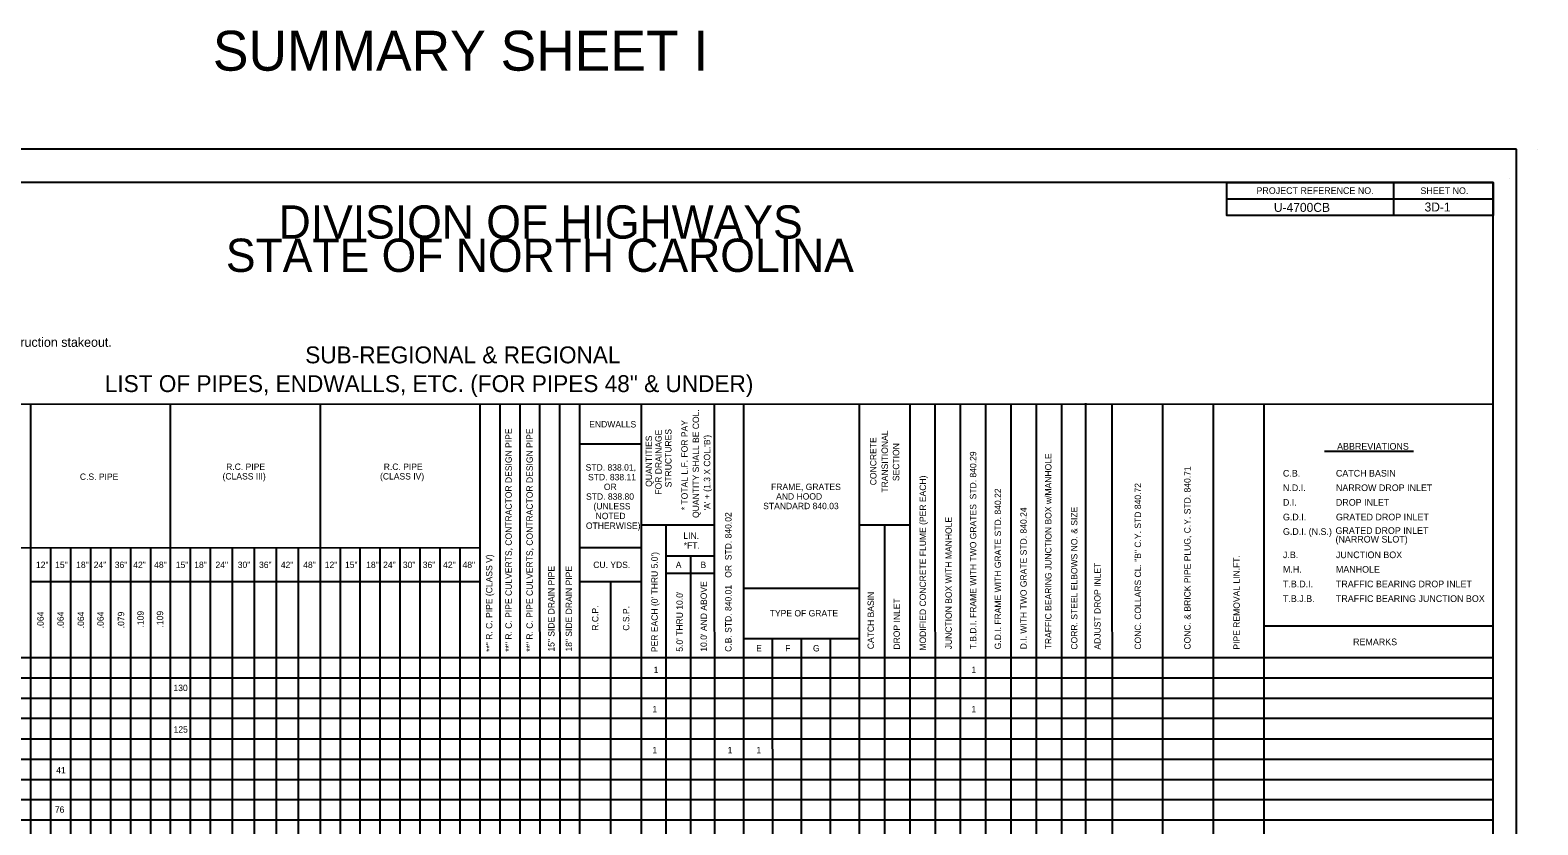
# Model space of a CAD drawing. Extents: x 809447 to 814738, y 647528 to 651206.
# Drawn here: x 810014 to 811147, y 650609 to 651206 of the extents above; entities that cross this region are included whole.
import ezdxf

# ---------------------------------------------------------------- set-up
doc = ezdxf.new("R2010")
doc.units = 0
doc.layers.add('Default', color=7, linetype='Continuous')
doc.layers.add('Old_Level_44', color=7, linetype='Continuous')

msp = doc.modelspace()

# ---------------------------------------------------------------- linework, layer by layer
at = {"layer": 'Default'}
for p, q in [((811147.1, 651116.9), (811147.1, 651116.9)), ((811147.1, 651116.9), (811147.1, 651116.9)), ((811147.1, 651116.9), (811147.1, 651116.9)), ((811038.6, 651091.9), (811038.6, 651066.9)), ((811126.1, 651094.5), (811126.1, 651094.5)), ((811126.1, 651094.5), (811126.1, 651094.5)), ((811126.1, 651094.5), (811126.1, 651094.5)), ((810913.5, 651079.4), (811113.6, 651079.4)), ((811113.6, 650925.1), (809613.6, 650925)), ((810014.9, 650154.3), (810014.9, 650925)), ((810119.9, 650154.3), (810119.9, 650925)), ((810232.5, 650154.3), (810232.4, 650925.1)), ((810352.5, 650154.3), (810352.4, 650925.1)), ((810367.5, 650154.3), (810367.4, 650925.1)), ((810382.5, 650154.3), (810382.4, 650925.1)), ((810397.5, 650154.3), (810397.4, 650925.1)), ((810412.5, 650154.3), (810412.4, 650925.1)), ((810427.5, 650154.3), (810427.4, 650925.1)), ((810427.4, 650154.3), (810427.4, 650925.1)), ((810427.5, 650154.3), (810427.4, 650925.1)), ((810473.7, 650154.3), (810473.6, 650925)), ((810528.7, 650154.3), (810528.6, 650925)), ((810528.7, 650154.3), (810528.6, 650925)), ((810550.5, 650154.3), (810550.5, 650925)), ((810637.5, 650154.3), (810637.4, 650925)), ((810675.5, 650154.3), (810675.4, 650925)), ((810694.5, 650154.3), (810694.4, 650925)), ((810713.5, 650154.3), (810713.4, 650925)), ((810732.5, 650154.3), (810732.4, 650925)), ((810751.5, 650154.3), (810751.4, 650925)), ((810770.5, 650154.3), (810770.4, 650925)), ((810789.5, 650154.3), (810789.4, 650925)), ((810807.6, 650155.2), (810807.5, 650925.9)), ((810827.5, 650154.3), (810827.4, 650925)), ((810827.5, 650154.3), (810827.4, 650925)), ((810865.5, 650154.3), (810865.4, 650925)), ((810865.5, 650154.3), (810865.4, 650925)), ((810903.5, 650154.3), (810903.4, 650925)), ((810903.5, 650154.3), (810903.4, 650925)), ((810941.5, 650154.3), (810941.4, 650925)), ((810941.5, 650154.3), (810941.4, 650925)), ((810473.6, 650895.1), (810427.4, 650895.1)), ((811053.7, 650889.6), (810986.7, 650889.6)), ((810527.4, 650834.3), (810473.6, 650834.3)), ((810492.3, 650154.3), (810492.2, 650834.3)), ((810675.4, 650834.3), (810637.4, 650834.3)), ((810656.5, 650154.3), (810656.4, 650834.3)), ((810352.4, 650817.2), (809834.9, 650817.1)), ((810029.9, 650154.3), (810029.9, 650817.1)), ((810044.9, 650154.3), (810044.9, 650817.2)), ((810059.9, 650154.3), (810059.9, 650817.1)), ((810074.9, 650154.3), (810074.9, 650817.2)), ((810089.9, 650154.3), (810089.9, 650817.1)), ((810104.9, 650154.3), (810104.9, 650817.2)), ((810119.9, 650154.3), (810119.9, 650817.1)), ((810134.9, 650154.3), (810134.9, 650817.2)), ((810149.9, 650154.3), (810149.9, 650817.2)), ((810166.4, 650154.3), (810166.4, 650817.2)), ((810182.9, 650154.3), (810182.9, 650817.2)), ((810199.4, 650154.3), (810199.4, 650817.2)), ((810215.9, 650154.3), (810215.9, 650817.2)), ((810232.4, 650154.3), (810232.4, 650817.2)), ((810247.4, 650154.3), (810247.4, 650817.2)), ((810262.4, 650154.3), (810262.4, 650817.2)), ((810277.4, 650154.3), (810277.4, 650817.2)), ((810292.4, 650154.3), (810292.4, 650817.2)), ((810307.4, 650154.3), (810307.4, 650817.2)), ((810322.4, 650154.3), (810322.4, 650817.2)), ((810337.4, 650154.3), (810337.4, 650817.2)), ((810352.4, 650154.3), (810352.4, 650817.2)), ((810473.6, 650817.2), (810427.4, 650817.2)), ((810528.6, 650811.1), (810492.2, 650811.1)), ((810510.9, 650154.3), (810510.8, 650811.1)), ((810528.6, 650797.9), (810492.2, 650797.9)), ((810352.4, 650791.8), (810014.9, 650791.8)), ((810014.9, 650154.3), (810014.9, 650791.8)), ((810473.6, 650791.8), (810427.4, 650791.8)), ((810450.6, 650154.3), (810450.5, 650791.8)), ((810637.4, 650786.8), (810550.5, 650786.8)), ((811113.6, 650758.5), (810941.4, 650758.5)), ((810637.4, 650749), (810550.5, 650749)), ((810572.3, 650154.3), (810572.2, 650749)), ((810594, 650154.3), (810593.9, 650749)), ((810615.7, 650154.3), (810615.7, 650749)), ((811113.6, 650734.7), (809613.6, 650734.7)), ((811113.6, 650719.4), (809613.6, 650719.4)), ((811113.6, 650704.1), (809613.6, 650704.1)), ((811113.6, 650688.9), (809613.6, 650688.9)), ((811113.6, 650673.6), (809613.6, 650673.6)), ((811113.6, 650658.3), (809613.6, 650658.3)), ((811113.6, 650643), (809613.6, 650643)), ((811113.6, 650627.8), (809613.6, 650627.8)), ((811113.6, 650612.5), (809613.6, 650612.5))]:
    msp.add_line(p, q, dxfattribs=at)
for points in [[(811131.1, 651116.9), (809447.1, 651116.9), (809447.1, 650016.9), (811131.1, 650016.9)], [(811113.6, 651091.9), (809613.6, 651091.9), (809613.6, 650041.9), (811113.6, 650041.9)], [(810913.5, 651091.9), (811113.6, 651091.9), (811113.6, 651066.9), (810913.5, 651066.9)]]:
    msp.add_lwpolyline(points, close=True, dxfattribs=at)

# ---------------------------------------------------------------- texts
for s, height, rotation, p in [('PROJECT REFERENCE NO.', 5, 360, (810935.7, 651083.2)), ('SHEET NO.', 5, 360, (811058.9, 651083.1)), ('DIVISION OF HIGHWAYS', 25, 360, (810201, 651049.6)), ('U-4700CB', 6.75, 360, (810948.8, 651069.7)), ('3D-1', 6.75, 360, (811062, 651070)), ('STATE OF NORTH CAROLINA', 25, 360, (810161.4, 651024.6)), ('QUANTITY SHALL BE COL.', 4.8, 90, (810516.9, 650839.7)), ('* TOTAL L.F. FOR PAY', 4.8, 90, (810508.4, 650845.5)), ('**" R. C. PIPE CULVERTS, CONTRACTOR DESIGN PIPE', 4.8, 90, (810376.2, 650739.2)), ('**" R. C. PIPE CULVERTS, CONTRACTOR DESIGN PIPE', 4.8, 90, (810392, 650739.2)), ('QUANTITIES', 4.8, 90, (810481.6, 650863.1)), ('FOR DRAINAGE', 4.8, 90, (810488.8, 650857.2)), ('STRUCTURES', 4.8, 90, (810496.2, 650862.7)), ("'A' + (1.3 X COL.'B')", 4.8, 90, (810525.3, 650845.3)), ('CONCRETE', 4.8, 90, (810650.2, 650864.3)), ('TRANSITIONAL', 4.8, 90, (810658.8, 650858.7)), ('SECTION', 4.8, 90, (810667.3, 650867.4)), ('T.B.D.I. FRAME WITH TWO GRATES  STD. 840.29', 4.8, 90, (810725.2, 650741)), ('TRAFFIC BEARING JUNCTION BOX w/MANHOLE', 4.8, 90, (810781.7, 650741)), ('CONC. & BRICK PIPE PLUG, C.Y. STD. 840.71', 4.8, 90, (810886.2, 650740.8)), ('MODIFIED CONCRETE FLUME (PER EACH)', 4.8, 90, (810687.4, 650740)), ('CONC. COLLARS CL. "B" C.Y. STD 840.72', 4.8, 90, (810849, 650740.8)), ('G.D.I. FRAME WITH GRATE STD. 840.22', 4.8, 90, (810743.8, 650741)), ('C.B. STD. 840.01   OR  STD. 840.02', 4.8, 90, (810541.3, 650739.1)), ('D.I. WITH TWO GRATE STD. 840.24', 4.8, 90, (810763.1, 650741)), ('CORR. STEEL ELBOWS NO. & SIZE', 4.8, 90, (810801.2, 650740.8)), ('JUNCTION BOX WITH MANHOLE', 4.8, 90, (810706.8, 650741)), ('GRATED DROP INLET', 5, 0.0274, (810995.1, 650827.7)), ('(NARROW SLOT)', 5, 0.0274, (810995.1, 650821.2)), ('**" R. C. PIPE (CLASS V)', 4.8, 90, (810361.6, 650739.1)), ("PER EACH (0' THRU 5.0')", 4.799, 90.0369, (810485.9, 650738.9)), ('PIPE REMOVAL LIN.FT.', 4.8, 90, (810923.2, 650740.8)), ('15" SIDE DRAIN PIPE', 4.8, 90, (810408.3, 650739.3)), ('18" SIDE DRAIN PIPE', 4.8, 90, (810421.5, 650739.3)), ('ADJUST DROP INLET', 4.8, 90, (810818.6, 650740.8)), ("10.0' AND ABOVE", 4.8, 90, (810522.8, 650739.2)), ("5.0' THRU 10.0'", 4.8, 90, (810504.7, 650739.2)), ('CATCH BASIN', 4.8, 90, (810648.3, 650741.1)), ('DROP INLET', 4.8, 90, (810667.8, 650740.8)), ('.064', 4.8, 90, (810024.5, 650756.8)), ('.064', 4.8, 90, (810039.6, 650756.8)), ('.064', 4.8, 90, (810054.8, 650756.8)), ('.064', 4.8, 90, (810069.6, 650756.8)), ('.079', 4.8, 90, (810085, 650756.8)), ('.109', 4.8, 90, (810099.7, 650757.4)), ('.109', 4.8, 90, (810114.3, 650757.4)), ('R.C.P.', 4.8, 90, (810441.3, 650755)), ('C.S.P.', 4.8, 90, (810464.5, 650755))]:
    msp.add_text(s, height=height, rotation=rotation, dxfattribs=at).set_placement(p)
for s, height, p in [('NOTE: Invert Elevations are for Bid Purposes only and shall not be used for project construction stakeout.', 7, (809638.1, 650968.3)), ('SUB-REGIONAL & REGIONAL', 12.7, (810221, 650955.9)), ('LIST OF PIPES, ENDWALLS, ETC. (FOR PIPES 48" & UNDER)', 12.7, (810070.4, 650934.3)), ('ENDWALLS', 4.8, (810434.4, 650907.7)), ('ABBREVIATIONS', 5, (810996.3, 650891)), ('R.C. PIPE', 4.8, (810161.6, 650875.8)), ('R.C. PIPE', 4.8, (810280, 650875.8)), ('STD. 838.01,', 4.8, (810431.7, 650875.3)), ('C.B.', 5, (810955.6, 650870.8)), ('CATCH BASIN', 5, (810995.4, 650870.8)), ('C.S. PIPE', 4.8, (810051.7, 650868.3)), ('(CLASS III)', 4.8, (810158.9, 650868.6)), ('(CLASS IV)', 4.8, (810277.2, 650868.6)), ('STD. 838.11', 4.8, (810433.5, 650868)), ('OR', 4.8, (810445.4, 650860.7)), ('FRAME, GRATES', 4.8, (810571, 650860.7)), ('N.D.I.', 5, (810955.6, 650859.9)), ('NARROW DROP INLET', 5, (810995.4, 650859.9)), ('STD. 838.80', 4.8, (810432, 650853.4)), ('AND HOOD', 4.8, (810574.8, 650853.5)), ('D.I.', 5, (810955.6, 650848.9)), ('DROP INLET', 5, (810995.4, 650848.9)), ('(UNLESS', 4.8, (810437.6, 650846.1)), ('NOTED', 4.8, (810439.2, 650838.8)), ('STANDARD 840.03', 4.8, (810565.1, 650846.3)), ('G.D.I.', 5, (810955.6, 650837.9)), ('GRATED DROP INLET', 5, (810995.4, 650837.9)), ('OTHERWISE)', 4.8, (810431.9, 650831.5)), ('G.D.I. (N.S.)', 5, (810955.6, 650827)), ('*FT.', 4.8, (810505.4, 650816.7)), ('LIN.', 4.8, (810505.1, 650824)), ('J.B.', 5, (810955.6, 650809.5)), ('JUNCTION BOX', 5, (810995.4, 650809.5)), ('12"', 4.8, (810018.7, 650802.1)), ('15"', 4.8, (810033.1, 650802.1)), ('18"', 4.8, (810048.9, 650802.1)), ('24"', 4.8, (810062.1, 650802.1)), ('36"', 4.8, (810077.9, 650802.1)), ('42"', 4.8, (810091.8, 650802.1)), ('48"', 4.8, (810107.5, 650802.1)), ('15"', 4.8, (810123.8, 650802.1)), ('18"', 4.8, (810137.6, 650802.1)), ('24"', 4.8, (810153.6, 650802.1)), ('30"', 4.8, (810170.3, 650802.1)), ('36"', 4.8, (810186.3, 650802.1)), ('42"', 4.8, (810202.7, 650802.1)), ('48"', 4.8, (810219.5, 650802.1)), ('12"', 4.8, (810235.7, 650802.1)), ('15"', 4.8, (810250.9, 650802.1)), ('18"', 4.8, (810266.8, 650802.1)), ('24"', 4.8, (810279.5, 650802.1)), ('30"', 4.8, (810294.4, 650802.1)), ('36"', 4.8, (810309.3, 650802.1)), ('42"', 4.8, (810324.6, 650802.1)), ('48"', 4.8, (810339.2, 650802.1)), ('CU. YDS.', 4.8, (810437.4, 650802.1)), ('A', 4.8, (810499.4, 650802.1)), ('B', 4.8, (810518, 650802.1)), ('M.H.', 5, (810955.6, 650798.6)), ('MANHOLE', 5, (810995.4, 650798.6)), ('T.B.D.I.', 5, (810955.6, 650787.6)), ('TRAFFIC BEARING DROP INLET', 5, (810995.4, 650787.6)), ('T.B.J.B.', 5, (810955.6, 650776.6)), ('TRAFFIC BEARING JUNCTION BOX', 5, (810995.4, 650776.6)), ('TYPE OF GRATE', 4.8, (810570, 650765.7)), ('E', 4.8, (810559.8, 650739.4)), ('F', 4.8, (810581.6, 650739.4)), ('G', 4.8, (810602.5, 650739.4)), ('REMARKS', 5, (811008.3, 650744.1)), ('1', 4.8, (810482.8, 650723.2)), ('1', 4.8, (810721.6, 650723.2)), ('130', 4.8, (810122, 650709.6)), ('1', 4.8, (810481.9, 650693.7)), ('1', 4.8, (810721.6, 650693.7)), ('125', 4.8, (810122.1, 650678.4)), ('1', 4.8, (810481.9, 650662.9)), ('1', 4.8, (810538.4, 650662.9)), ('1', 4.8, (810560, 650662.9)), ('41', 4.8, (810033.9, 650647.7)), ('76', 4.8, (810032.9, 650618.2))]:
    msp.add_text(s, height=height, dxfattribs=at).set_placement(p)
at = {"layer": 'Old_Level_44'}
msp.add_text('SUMMARY SHEET I', height=30, rotation=360, dxfattribs=at).set_placement((810151.6, 651175.8))

doc.saveas('drawing.dxf')
